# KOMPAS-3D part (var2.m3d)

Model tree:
1. ВЗ
2. jcm
     Расстояние = 75
3. ВЗ 1
     Расстояние = 50
4. ВЗ 2
     Расстояние = 50
5. ВЗ 3
     Расстояние = 50
6. ВЗ 4
     Расстояние = 50
7. ВЗ 5
     Расстояние = 50
8. ВЗ 6
     Расстояние = 50
9. Эскиз:9
10. Операция выдавливания:4
     Расстояние 1 = 65; Расстояние 2 = 60
11. Эскиз:10
12. Операция выдавливания:5
     Расстояние 1 = 65; Расстояние 2 = 70
13. Булева операция:2
14. Эскиз:11
15. Операция выдавливания:6
     Расстояние 1 = 545; Расстояние 2 = 360
16. Булева операция:3
17. Зеркальное отражение:3
18. ВЗ 7
     Расстояние = 50
19. ВЗ  8
     Расстояние = 50
20. боковые понтоны
21. Эскиз:17
22. Эскиз:18
23. Эскиз:19
24. Эскиз:20
25. Эскиз:21
26. Правый киль
     Толщина стенки 1 = 1; Толщина стенки 2 = 1; Расстояние 1 = 7; Расстояние 2 = 360
27. Левый киль
28. Киль1
29. Эскиз:22
30. Операция выдавливания:9
     Расстояние 1 = 125; Расстояние 2 = 125
31. стабилизатор1
32. Эскиз:24
33. Операция выдавливания:10
     Расстояние 1 = 75; Расстояние 2 = 75
34. Эскиз:25
35. Эскиз:26
36. Эскиз:27
37. Эскиз:30
38. Операция по сечениям:1
     Толщина стенки 1 = 2; Толщина стенки 2 = 2
39. Эскиз:28
40. Кинематическая операция:6
     Толщина стенки 1 = 2; Толщина стенки 2 = 14
41. Эскиз:29
42. Операция выдавливания:11
     Расстояние 1 = 45; Расстояние 2 = 45
43. Булева операция:8
44. Кабина2
45. Корпус2
46. сопло
     Толщина стенки 1 = 2; Толщина стенки 2 = 2
47. турбина 2
48. сечение воздухозаборника
49. Смещенная плоскость:1
     Расстояние = 40
50. плоскости
51. траектория воздухозаборника
52. Кинематическая операция:10
     Толщина стенки 1 = 4; Толщина стенки 2 = 2
53. Кинематическая операция:12
     Толщина стенки 1 = 4; Толщина стенки 2 = 2
54. Кинематическая операция:13
     Толщина стенки 1 = 4; Толщина стенки 2 = 2
55. Булева операция:15
56. Зеркальное отражение:4
57. воздухозаборник
